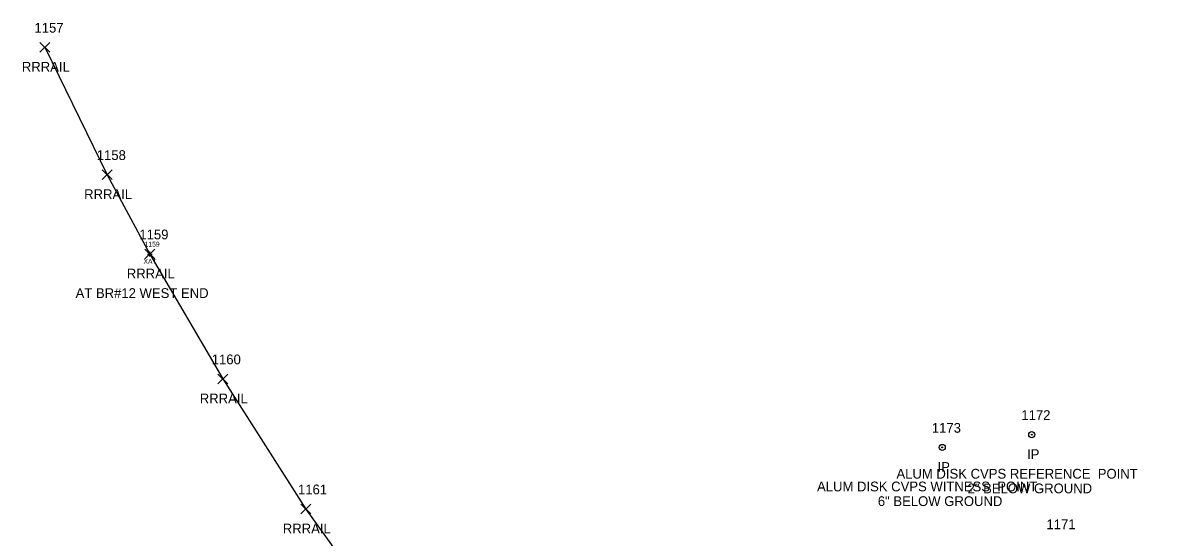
# Model space of a CAD drawing. Extents: x 1764889 to 1767296, y 695936 to 698960.
# Drawn here: x 1764947.9 to 1765182.1, y 696222.3 to 696327.5 of the extents above; entities that cross this region are included whole.
import ezdxf

# ---------------------------------------------------------------- set-up
doc = ezdxf.new("R2010")
doc.units = 0
for name, color, linetype in [('B_A', 7, 'Continuous'), ('B_I', 7, 'Continuous'), ('B_TIC', 7, 'Continuous'), ('M_A', 7, 'Continuous'), ('M_C', 7, 'Continuous'), ('M_I', 7, 'Continuous'), ('MPIR', 7, 'Continuous'), ('R_A', 7, 'Continuous'), ('R_C', 7, 'Continuous'), ('R_I', 7, 'Continuous'), ('R_TIC', 7, 'Continuous'), ('RR', 7, 'Continuous')]:
    doc.layers.add(name, color=color, linetype=linetype)

msp = doc.modelspace()

# ---------------------------------------------------------------- linework, layer by layer
at = {"layer": 'B_TIC'}
msp.add_line((1764973.9, 696280.22), (1764973.98, 696280.22), dxfattribs=at)
for points in [[(1764973.4, 696280.22), (1764974.4, 696280.22)], [(1764973.9, 696279.72), (1764973.9, 696280.72)]]:
    msp.add_lwpolyline(points, dxfattribs=at)
at = {"layer": 'MPIR'}
for centre, radius in [((1765154.24, 696243.25), 0.625), ((1765154.24, 696243.25), 0.0833), ((1765135.93, 696240.64), 0.625), ((1765135.93, 696240.64), 0.0833)]:
    msp.add_circle(centre, radius, dxfattribs=at)
at = {"layer": 'R_TIC'}
for points in [[(1764951.43, 696321.53), (1764953.43, 696323.53)], [(1764953.43, 696321.53), (1764951.43, 696323.53)], [(1764951.43, 696321.53), (1764953.43, 696323.53)], [(1764953.43, 696321.53), (1764951.43, 696323.53)], [(1764964.18, 696295.46), (1764966.18, 696297.46)], [(1764966.18, 696295.46), (1764964.18, 696297.46)], [(1764972.9, 696279.22), (1764974.9, 696281.22)], [(1764974.9, 696279.22), (1764972.9, 696281.22)], [(1764987.82, 696253.65), (1764989.82, 696255.65)], [(1764989.82, 696253.65), (1764987.82, 696255.65)], [(1765004.8, 696227.03), (1765006.8, 696229.03)], [(1765006.8, 696227.03), (1765004.8, 696229.03)]]:
    msp.add_lwpolyline(points, dxfattribs=at)
at = {"layer": 'RR'}
msp.add_lwpolyline([(1764952.43, 696322.53), (1764965.18, 696296.46), (1764973.9, 696280.22), (1764988.82, 696254.65), (1765005.8, 696228.03), (1765022.45, 696204.87), (1765044.73, 696176.58), (1765062.87, 696155.39), (1765085.26, 696132.32), (1765108.4, 696110.02), (1765132.75, 696088.74), (1765155.49, 696070.71), (1765182.12, 696051.56)], dxfattribs=at)

# ---------------------------------------------------------------- texts
at = {"layer": 'B_A'}
msp.add_text('XAT', height=1, dxfattribs=at).set_placement((1764972.6, 696278.22))
at = {"layer": 'B_I'}
msp.add_text('1159', height=1, dxfattribs=at).set_placement((1764972.83, 696281.72))
at = {"layer": 'M_A'}
for p in [(1765153.28, 696238.25), (1765134.98, 696235.64)]:
    msp.add_text('IP', height=2, dxfattribs=at).set_placement(p)
at = {"layer": 'M_C'}
for s, p in [('ALUM DISK CVPS REFERENCE  POINT', (1765126.57, 696234.25)), ('ALUM DISK CVPS WITNESS  POINT', (1765110.33, 696231.64)), ('2" BELOW GROUND', (1765141.11, 696231.25)), ('6" BELOW GROUND', (1765122.76, 696228.64))]:
    msp.add_text(s, height=2, dxfattribs=at).set_placement(p)
at = {"layer": 'M_I'}
for s, p in [('1172', (1765152.11, 696246.25)), ('1173', (1765133.81, 696243.64)), ('1171', (1765157.24, 696223.9))]:
    msp.add_text(s, height=2, dxfattribs=at).set_placement(p)
at = {"layer": 'R_A'}
for p in [(1764947.73, 696317.53), (1764947.73, 696317.53), (1764960.47, 696291.46), (1764969.19, 696275.22), (1764984.11, 696249.65), (1765001.09, 696223.03)]:
    msp.add_text('RRRAIL', height=2, dxfattribs=at).set_placement(p)
at = {"layer": 'R_C'}
msp.add_text('AT BR#12 WEST END', height=2, dxfattribs=at).set_placement((1764958.72, 696271.22))
at = {"layer": 'R_I'}
for s, p in [('1157', (1764950.31, 696325.53)), ('1157', (1764950.31, 696325.53)), ('1158', (1764963.05, 696299.46)), ('1159', (1764971.76, 696283.22)), ('1160', (1764986.56, 696257.65)), ('1161', (1765004.2, 696231.03))]:
    msp.add_text(s, height=2, dxfattribs=at).set_placement(p)

doc.saveas('drawing.dxf')
